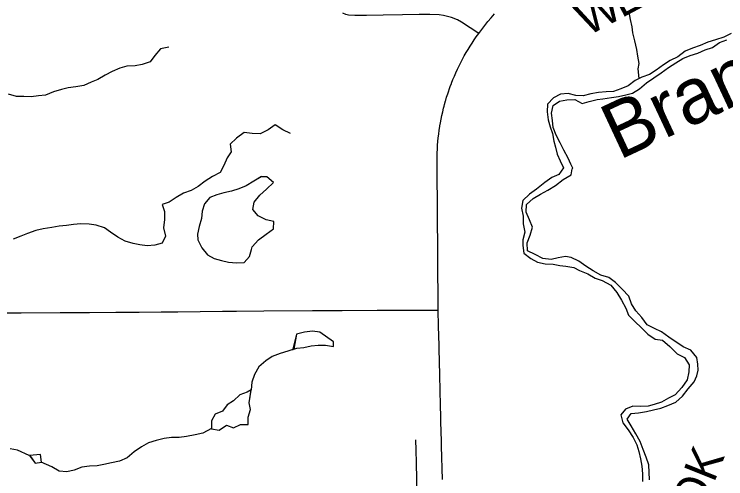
# Model space of a CAD drawing. Extents: x 0 to 34, y 0 to 22.
# Drawn here: x 5.585 to 6.189, y 16.688 to 17.083 of the extents above; entities that cross this region are included whole.
import ezdxf

# ---------------------------------------------------------------- set-up
doc = ezdxf.new("R2010")
doc.units = 0
for name, color, linetype in [('GM_X_County_Road', 7, 'Continuous'), ('GM_X_County_Road_Text', 7, 'Continuous'), ('GM_X_Minor_Lake', 7, 'Continuous'), ('GM_X_Minor_River', 7, 'Continuous'), ('GM_X_Minor_River_Text', 7, 'Continuous'), ('GM_X_State_Route', 7, 'Continuous'), ('GM_X_Township_Road', 7, 'Continuous'), ('GM_X_Township_Road_Text', 7, 'Continuous')]:
    doc.layers.add(name, color=color, linetype=linetype)

msp = doc.modelspace()

# ---------------------------------------------------------------- linework, layer by layer
at = {"layer": 'GM_X_County_Road'}
msp.add_lwpolyline([(5.57861, 16.82899), (5.59058, 16.82906), (5.62365, 16.82927), (5.64862, 16.82949), (5.6711, 16.82963), (5.69071, 16.82976), (5.70947, 16.82994), (5.72373, 16.83007), (5.76165, 16.83052), (5.7736, 16.83061), (5.79682, 16.83074), (5.83814, 16.83097), (5.86334, 16.83115), (5.89296, 16.83128), (5.94484, 16.83128)], dxfattribs=at)
at = {"layer": 'GM_X_Minor_Lake'}
for points in [[(5.7947, 16.94477), (5.78827, 16.94078), (5.78165, 16.93698), (5.7756, 16.93432), (5.76917, 16.93242), (5.76274, 16.9309), (5.75688, 16.92938), (5.75083, 16.92691), (5.74648, 16.92178), (5.7444, 16.91533), (5.74384, 16.90907), (5.74176, 16.90243), (5.74044, 16.89598), (5.74063, 16.89105), (5.74403, 16.88441), (5.74877, 16.87834), (5.75444, 16.87531), (5.76068, 16.87361), (5.76674, 16.87209), (5.77355, 16.87153), (5.77998, 16.87172), (5.7847, 16.87684), (5.7864, 16.88292)], [(5.7944, 16.94457), (5.78827, 16.94078), (5.78165, 16.93698), (5.7756, 16.93432), (5.76917, 16.93242), (5.76274, 16.9309), (5.75688, 16.92938), (5.75083, 16.92691), (5.74648, 16.92178), (5.7444, 16.91533), (5.74384, 16.90907), (5.74176, 16.90243), (5.74044, 16.89598), (5.74063, 16.89105), (5.74403, 16.88441), (5.74877, 16.87834), (5.75444, 16.87531), (5.76068, 16.87361), (5.76674, 16.87209), (5.77355, 16.87153), (5.77998, 16.87172), (5.7847, 16.87684), (5.7864, 16.88292)], [(5.7864, 16.88292), (5.78678, 16.88519), (5.79226, 16.89108), (5.79888, 16.89601), (5.80512, 16.90038), (5.80531, 16.90664), (5.79869, 16.90815), (5.79207, 16.91137), (5.78753, 16.91687), (5.78866, 16.92314), (5.79338, 16.92902), (5.79906, 16.93414), (5.80511, 16.93984), (5.79924, 16.94458), (5.7944, 16.94457)], [(5.7864, 16.88292), (5.78678, 16.88519), (5.79226, 16.89108), (5.79888, 16.89601), (5.80512, 16.90038), (5.80531, 16.90664), (5.79869, 16.90815), (5.79207, 16.91137), (5.78753, 16.91687), (5.78866, 16.92314), (5.79338, 16.92902), (5.79906, 16.93414), (5.80511, 16.93984), (5.79924, 16.94458), (5.79395, 16.94457)], [(5.85585, 16.80062), (5.85604, 16.80441), (5.84431, 16.81275), (5.83807, 16.81351), (5.83126, 16.81256), (5.82445, 16.81104), (5.82106, 16.79754)], [(5.85585, 16.80062), (5.85604, 16.80441), (5.84431, 16.81275), (5.83807, 16.81351), (5.83126, 16.81256), (5.82445, 16.81104), (5.82217, 16.79828)], [(5.82217, 16.79828), (5.82483, 16.79908), (5.83088, 16.79966), (5.83694, 16.80099), (5.84299, 16.80156), (5.84923, 16.80175), (5.85585, 16.80062)], [(5.78609, 16.76367), (5.78267, 16.76169), (5.77642, 16.7596), (5.77113, 16.75428), (5.76565, 16.75087), (5.76168, 16.74574), (5.75544, 16.74308), (5.75241, 16.73739)], [(5.75241, 16.73739), (5.75242, 16.73075), (5.75885, 16.72961), (5.76509, 16.7336), (5.77095, 16.73133), (5.777, 16.73437), (5.78343, 16.73418), (5.78343, 16.74044), (5.78532, 16.74708), (5.78418, 16.75258), (5.78605, 16.76365)], [(5.78605, 16.76365), (5.78267, 16.76169), (5.77642, 16.7596), (5.77113, 16.75428), (5.76565, 16.75087), (5.76168, 16.74574), (5.75544, 16.74308), (5.75241, 16.73739)], [(5.75241, 16.73739), (5.75242, 16.73075), (5.75885, 16.72961), (5.76509, 16.7336), (5.77095, 16.73133), (5.777, 16.73437), (5.78343, 16.73418), (5.78343, 16.74044), (5.78532, 16.74708), (5.78418, 16.75258), (5.78603, 16.76356)], [(5.59761, 16.70805), (5.60244, 16.70145), (5.60792, 16.7024), (5.60697, 16.70885)], [(5.60697, 16.70885), (5.59761, 16.70805)], [(5.59789, 16.7079), (5.60244, 16.70145), (5.60792, 16.7024), (5.60697, 16.70885), (5.59761, 16.70805)]]:
    msp.add_lwpolyline(points, dxfattribs=at)
at = {"layer": 'GM_X_Minor_River'}
for points in [[(6.11568, 17.02806), (6.11473, 17.03614), (6.11575, 17.04091), (6.11447, 17.04714), (6.11378, 17.05282), (6.11209, 17.06018), (6.11042, 17.06697), (6.10974, 17.07188), (6.10828, 17.07811), (6.10719, 17.08435)], [(6.19393, 17.06616), (6.18755, 17.0632), (6.18041, 17.0608), (6.17401, 17.05898), (6.16744, 17.05621), (6.16105, 17.05382), (6.15486, 17.05124), (6.14851, 17.04658), (6.14214, 17.04324), (6.13633, 17.03972), (6.13018, 17.03506), (6.12457, 17.03136), (6.11799, 17.02916), (6.11217, 17.0264), (6.1062, 17.02174), (6.10001, 17.01916), (6.09399, 17.01716), (6.08776, 17.01667), (6.08114, 17.01618), (6.07455, 17.01492), (6.06796, 17.01329), (6.0619, 17.01356), (6.05544, 17.01535), (6.04883, 17.01485), (6.04283, 17.01171), (6.03782, 17.00631), (6.03755, 16.99986), (6.03824, 16.99304), (6.04005, 16.987), (6.04204, 16.98134), (6.04329, 16.97491), (6.0447, 16.96982), (6.04613, 16.96396)], [(6.05779, 16.94614), (6.05887, 16.9513), (6.05926, 16.95208), (6.05763, 16.95525), (6.05546, 16.96052), (6.05175, 16.96709), (6.04842, 16.97349), (6.04528, 16.98007), (6.04271, 16.98648), (6.04203, 16.99253), (6.04117, 16.99878), (6.04257, 17.00507), (6.04798, 17.00896), (6.05421, 17.01001), (6.06101, 17.01032), (6.06712, 17.00683), (6.07334, 17.00845), (6.07992, 17.01028), (6.08483, 17.01093), (6.09219, 17.01201), (6.09804, 17.01287), (6.10444, 17.01412), (6.11009, 17.01574), (6.11589, 17.01926), (6.12204, 17.02448), (6.12821, 17.02877), (6.13438, 17.03286), (6.14073, 17.03734), (6.1469, 17.04124), (6.15288, 17.04514), (6.15908, 17.04752), (6.16548, 17.04953), (6.17167, 17.05249), (6.17806, 17.0545), (6.18404, 17.05859), (6.19005, 17.06097)], [(5.71605, 17.05461), (5.70909, 17.05331), (5.70411, 17.0477), (5.70026, 17.04229), (5.69351, 17.03986), (5.6873, 17.03877), (5.68049, 17.03861), (5.6743, 17.03676), (5.66793, 17.03396), (5.66195, 17.03097), (5.65579, 17.02723), (5.64998, 17.02501), (5.64381, 17.02221), (5.63703, 17.02091), (5.63062, 17.02019), (5.62479, 17.01873), (5.61803, 17.01668), (5.61128, 17.01386), (5.60524, 17.01335), (5.59903, 17.01244), (5.59277, 17.01287), (5.58653, 17.01291), (5.57968, 17.01484)], [(5.81948, 16.98131), (5.81297, 16.98457), (5.80626, 16.98878), (5.80049, 16.98447), (5.79376, 16.98109), (5.78676, 16.9815), (5.77993, 16.98229), (5.77362, 16.9774), (5.76825, 16.97234), (5.76896, 16.96591), (5.76568, 16.96071), (5.7628, 16.95419), (5.75954, 16.94823), (5.75318, 16.94486), (5.74703, 16.94093), (5.74109, 16.93642), (5.73493, 16.93287), (5.72855, 16.93082), (5.7222, 16.92707), (5.71624, 16.92314), (5.71043, 16.92111), (5.71246, 16.91508), (5.71242, 16.90825), (5.71164, 16.9014), (5.71331, 16.89423), (5.71043, 16.88828), (5.70403, 16.88662), (5.69762, 16.88609), (5.69136, 16.88689), (5.68566, 16.8879), (5.679, 16.88983), (5.67268, 16.89329), (5.66634, 16.89751), (5.66134, 16.90138), (5.65429, 16.90349), (5.64822, 16.90449), (5.6414, 16.90471), (5.63499, 16.90418), (5.62896, 16.90328), (5.62292, 16.90257), (5.61651, 16.90167), (5.60935, 16.90055), (5.60296, 16.89908), (5.59602, 16.89645), (5.59021, 16.89423), (5.58365, 16.8918)], [(6.04613, 16.96396), (6.04869, 16.95812), (6.05145, 16.9521), (6.04738, 16.94653), (6.04137, 16.94415), (6.03559, 16.93968), (6.02831, 16.93405), (6.02252, 16.92997), (6.01695, 16.92437), (6.01573, 16.91808), (6.01718, 16.91109), (6.0171, 16.90464), (6.01855, 16.89764), (6.01697, 16.89098), (6.01686, 16.88623), (6.01773, 16.8798), (6.02367, 16.87535), (6.0294, 16.87203), (6.03586, 16.87082), (6.04248, 16.87037), (6.04837, 16.86933), (6.05329, 16.86885), (6.06012, 16.86764), (6.06508, 16.86507), (6.07213, 16.86216), (6.07825, 16.85847), (6.08433, 16.85668), (6.09159, 16.85264), (6.09681, 16.84647), (6.10071, 16.8399), (6.10423, 16.83313), (6.10661, 16.8271), (6.12315, 16.81107), (6.12928, 16.80682), (6.13554, 16.80579), (6.14188, 16.8004), (6.14785, 16.79443), (6.15433, 16.79113), (6.15804, 16.78494), (6.15776, 16.77905), (6.15637, 16.77219), (6.15195, 16.76567), (6.14638, 16.7595), (6.14057, 16.75655), (6.13458, 16.75322), (6.12837, 16.75121), (6.12328, 16.74999), (6.11667, 16.74968), (6.11043, 16.74976), (6.10404, 16.74718), (6.09997, 16.74237), (6.10179, 16.73576), (6.10643, 16.72977), (6.1107, 16.72339), (6.11384, 16.717), (6.11545, 16.71133), (6.1167, 16.70509), (6.11794, 16.69905), (6.11862, 16.69242), (6.11855, 16.68596)], [(6.12458, 16.68721), (6.12397, 16.7001), (6.12159, 16.70651), (6.11921, 16.71311), (6.11644, 16.71989), (6.11292, 16.72647), (6.10883, 16.73303), (6.10551, 16.73886), (6.10883, 16.74366), (6.11525, 16.74415), (6.12185, 16.74541), (6.12788, 16.74665), (6.1341, 16.74809), (6.14011, 16.75047), (6.14687, 16.75325), (6.15264, 16.75828), (6.15745, 16.76462), (6.16245, 16.77059), (6.16463, 16.77557), (6.16568, 16.78033), (6.1654, 16.78563), (6.16473, 16.79131), (6.15952, 16.79748), (6.15304, 16.80021), (6.14079, 16.80835), (6.13466, 16.81298), (6.12874, 16.81591), (6.12245, 16.81884), (6.11799, 16.82502), (6.11278, 16.83081), (6.10909, 16.83663), (6.10689, 16.84323), (6.1013, 16.8492), (6.09571, 16.85498), (6.08978, 16.85905), (6.08312, 16.86121), (6.07662, 16.86489), (6.07031, 16.86877), (6.06438, 16.87284), (6.05789, 16.87614), (6.05315, 16.87681), (6.04693, 16.87594), (6.0409, 16.87451), (6.03389, 16.87515), (6.0274, 16.87864), (6.02091, 16.88175), (6.0206, 16.88857), (6.02314, 16.89507), (6.02491, 16.90174), (6.02253, 16.90815), (6.01977, 16.91455), (6.01984, 16.92119), (6.02561, 16.92623), (6.03179, 16.92975), (6.03816, 16.93328), (6.04452, 16.93718), (6.05124, 16.94223), (6.05779, 16.94614)], [(5.82217, 16.79828), (5.81729, 16.79665), (5.81072, 16.7946), (5.80398, 16.79198), (5.79838, 16.78843), (5.79264, 16.78337), (5.78882, 16.77664), (5.7867, 16.77033), (5.78609, 16.76367)], [(5.75223, 16.73079), (5.74496, 16.72705), (5.73837, 16.72557), (5.73103, 16.72407), (5.72481, 16.72336), (5.71819, 16.72339), (5.71197, 16.72249), (5.7052, 16.72082), (5.69882, 16.71877), (5.69284, 16.71541), (5.6867, 16.71109), (5.68077, 16.70602), (5.67421, 16.70321), (5.66725, 16.70172), (5.66085, 16.70044), (5.65521, 16.69917), (5.64859, 16.69902), (5.64218, 16.69811), (5.63563, 16.69549), (5.62942, 16.69402), (5.62279, 16.69462), (5.61665, 16.69828), (5.60767, 16.70239)], [(5.5975, 16.70805), (5.58758, 16.71259), (5.58112, 16.71377)]]:
    msp.add_lwpolyline(points, dxfattribs=at)
at = {"layer": 'GM_X_State_Route'}
msp.add_line((5.94484, 16.83128), (5.94455, 16.87696), dxfattribs=at)
for points in [[(5.94455, 16.87696), (5.94454, 16.87846), (5.94404, 16.95157), (5.94395, 16.95543), (5.94406, 16.96501), (5.94421, 16.9682), (5.94441, 16.97139), (5.94467, 16.97457), (5.94499, 16.97775), (5.94536, 16.98092), (5.94578, 16.98409), (5.94626, 16.98724), (5.94636, 16.98784), (5.94679, 16.99039), (5.94738, 16.99353), (5.94803, 16.99666), (5.94873, 16.99977), (5.94948, 17.00288), (5.94994, 17.00463), (5.95029, 17.00597), (5.95115, 17.00904), (5.95131, 17.00955), (5.95207, 17.0121), (5.95304, 17.01514), (5.95517, 17.02128), (5.95613, 17.02384), (5.95626, 17.02417), (5.95744, 17.02713), (5.95867, 17.03008), (5.95995, 17.033), (5.96128, 17.03591), (5.96266, 17.03879), (5.96409, 17.04164), (5.96558, 17.04447), (5.9671, 17.04727), (5.96869, 17.05005), (5.97031, 17.05279), (5.97199, 17.05551), (5.97371, 17.0582), (5.97548, 17.06086), (5.9773, 17.06349), (5.9794, 17.06642), (5.98103, 17.06861), (5.98458, 17.07319), (5.98723, 17.07646), (5.98994, 17.07968), (5.99271, 17.08286)], [(5.94567, 16.80135), (5.94523, 16.81792), (5.94484, 16.83128)], [(5.94854, 16.68771), (5.9483, 16.6969), (5.94806, 16.70652), (5.94781, 16.71592), (5.94769, 16.72079), (5.94766, 16.72197), (5.94754, 16.72659), (5.94724, 16.73824), (5.9472, 16.73972), (5.94689, 16.75181), (5.94669, 16.76195), (5.94665, 16.76371), (5.94637, 16.77565), (5.94629, 16.7785), (5.9461, 16.7856), (5.94605, 16.7873), (5.94573, 16.79884), (5.94567, 16.80135)]]:
    msp.add_lwpolyline(points, dxfattribs=at)
at = {"layer": 'GM_X_Township_Road'}
for points in [[(5.9794, 17.06642), (5.97204, 17.07119), (5.9648, 17.07593), (5.96132, 17.07776), (5.95632, 17.07973), (5.94953, 17.0816), (5.94582, 17.08205), (5.93777, 17.08241), (5.92871, 17.08254), (5.91473, 17.08225), (5.89812, 17.08193), (5.88387, 17.0817), (5.87408, 17.08148), (5.86877, 17.08175), (5.86658, 17.08229), (5.86399, 17.08354)], [(5.92798, 16.64461), (5.92711, 16.6739), (5.92637, 16.70188), (5.92614, 16.71237), (5.9259, 16.72135)]]:
    msp.add_lwpolyline(points, dxfattribs=at)

# ---------------------------------------------------------------- texts
at = {"layer": 'GM_X_County_Road_Text'}
for s, rotation, p in [('E', 28.13903, (6.10067, 17.07916)), ('W', 28.13661, (6.07165, 17.06364))]:
    msp.add_text(s, height=0.02841, rotation=rotation, dxfattribs=at).set_placement(p)
at = {"layer": 'GM_X_Minor_River_Text'}
msp.add_text('Branch', height=0.04737, rotation=25.05039, dxfattribs=at).set_placement((6.09857, 16.95855))
at = {"layer": 'GM_X_Township_Road_Text'}
msp.add_text('COOK', height=0.028409, rotation=68.10916, dxfattribs=at).set_placement((6.14699, 16.60396))

doc.saveas('drawing.dxf')
